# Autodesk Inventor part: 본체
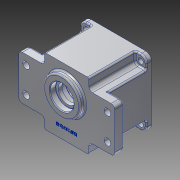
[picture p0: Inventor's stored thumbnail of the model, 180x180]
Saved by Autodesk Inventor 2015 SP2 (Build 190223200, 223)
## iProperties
Created: 2015-06
Part Number: 본체
Material: 알루미늄 6061
Document SubType Name: Modeling
Designer: AMC
Density: 2.7 g/cm^3
Appearance: 알루미늄 - 평지
Mass: 702.824 g
Surface Area: 672.969 cm^2
Volume: 260.305 cm^3
Author: AMC
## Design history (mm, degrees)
sketch "스케치1"
  geometry: L1 (45, 45)-(-45, 45); L2 (-45, 45)-(-45, -45); L3 (-45, -45)-(45, -45); L4 (45, -45)-(45, 45); 3 further points
  constraints: 8 end point, 2 midpoint, 2 parallel, 2 perpendicular, 1 horizontal, 1 horizontal alignment, 1 vertical alignment
  dimensions: "d0" = 90 distance of L1.start L1.end
extrude "돌출1" new body sketch "스케치1" distance "d1" = 70; taper "d2" = 0 deg
sketch "스케치2"
  geometry: L1 (-65, 30)-(65, 30); L2 (65, 30)-(65, -30); L3 (65, -30)-(-65, -30); L4 (-65, -30)-(-65, 30); 3 further points
  constraints: 8 end point, 2 midpoint, 2 parallel, 1 horizontal, 1 horizontal alignment, 1 perpendicular, 1 vertical alignment
  dimensions: "d3" = 130 distance of L2.end L3.end; "d4" = 60 distance of L1.end L2.end
extrude "돌출2" join sketch "스케치2" distance "d5" = 12; taper "d6" = 0 deg
sketch "스케치3"
  geometry: L1 (-45, 45)-(45, 45) reference; L2 (45, 45)-(45, -45) reference; L3 (45, 30)-(30, 30); L4 (30, 30)-(30, 45); 1 further point
  constraints: 4 end point, 2 perpendicular, 2 point on line
  dimensions: "d7" = 15 distance between parallel lines of L1 L3; "d8" = 30 distance from line of point (0, 0) L4
extrude "돌출3" cut sketch "스케치3" distance "d9" = 63; taper "d10" = 0 deg
sketch "스케치4"
  geometry: C1 r 25 at (0, 11); 1 further point
  constraints: 1 centre point, 1 vertical alignment
  dimensions: "d14" = 50 diameter of C1; "d15" = 11 distance of point (0, 0) C1.centre
extrude "돌출4" join sketch "스케치4" distance "d16" = 7; taper "d17" = 0 deg
fillet "모깎기1" dims "d18" = 5
fillet "모깎기2" dims "d19" = 8
sketch "스케치5"
  geometry: 3 further points
  constraints: 1 vertical alignment
  dimensions: "d20" = 35 distance of point (55, -17.5) point (55, 17.5); "d21" = 55 horizontal distance of point (0, 0) point (55, 17.5); "d22" = 17.5 vertical distance of point (55, 17.5) point (0, 0)
hole "구멍1" sketch "스케치5" at (55, 17.5), (55, -17.5) diameter "d23" = 9; stored, may be unused: countersink angle "d27" = 90 deg, drill point angle "d29" = 118 deg; dims "d24" = 6, "d25" = 4, "d26" = 2, "d28" = 8
sketch "스케치6"
  geometry: 1 further point
hole "구멍2" sketch "스케치6" at (0, 0) diameter "d30" = 78; stored, may be unused: countersink angle "d34" = 90 deg, drill point angle "d36" = 0 deg; dims "d31" = 6, "d32" = 80, "d33" = 9, "d35" = 61
sketch "스케치7"
  geometry: C1 r 25 at (0, -11) reference; C2 r 20.5 at (0, -11); 1 further point
  constraints: 1 centre point, 1 coincident
  dimensions: "d37" = 41 diameter of C2
extrude "돌출5" join sketch "스케치7" distance "d38" = 7; taper "d39" = 0 deg
hole "구멍3" diameter "d42" = 25; stored, may be unused: countersink angle "d46" = 90 deg, drill point angle "d48" = 118 deg; dims "d40" = 10, "d41" = 10, "d43" = 6, "d44" = 32, "d45" = 8, "d47" = 61
hole "구멍4" diameter "d51" = 35; stored, may be unused: countersink angle "d55" = 90 deg, drill point angle "d57" = 0 deg; dims "d49" = 10, "d50" = 10, "d52" = 6, "d53" = 32, "d54" = 8, "d56" = 10
sketch "스케치8"
  geometry: C1 r 14 at (0, 20); 1 further point
  constraints: 1 centre point, 1 vertical alignment
  dimensions: "d58" = 20 distance of point (0, 0) C1.centre; "d59" = 28 diameter of C1
extrude "돌출6" join sketch "스케치8" distance "d60" = 7; taper "d61" = 0 deg
hole "구멍5" diameter "d64" = 19; stored, may be unused: countersink angle "d68" = 90 deg, drill point angle "d70" = 0 deg; dims "d62" = 10, "d63" = 10, "d65" = 6, "d66" = 22, "d67" = 7, "d69" = 8
fillet "모깎기3" dims "d71" = 0.3
chamfer "모따기1" distance "d72" = 1; stored, may be unused: second distance "d73" = 2, angle "d74" = 45 deg
sketch "스케치9"
  geometry: L1 (0, 0)-(24.749, -24.749); L2 (0, 0)-(35, 0); L3 (22.066, -27.716)-(24.749, -30.141); L4 (27.716, -22.066)-(30.141, -24.749); A1 r 4 centre (24.749, -24.749) between (27.716, -22.066) and (22.066, -27.716); A2 r 39 centre (0, 0) between (24.749, -30.141) and (30.141, -24.749) reference; A3 r 39 centre (0, 0) between (24.749, -30.141) and (30.141, -24.749) reference
  constraints: 8 end point, 6 point on circle, 2 tangent, 1 centre point, 1 coincident, 1 equal length, 1 horizontal, 1 horizontal alignment, 1 vertical alignment
  dimensions: "d75" = 35 distance of L1.start L1.end; "d76" = 45 deg angle of L1 L2; "d77" = 8 diameter of A1
extrude "돌출7" join sketch "스케치9" distance "d78" = 52; taper "d79" = 0 deg
fillet "모깎기4" dims "d89" = 3.5
fillet "모깎기5" dims "d93" = 3
fillet "모깎기6" dims "d94" = 2
hole "구멍7" diameter "d97" = 7; stored, may be unused: countersink angle "d101" = 90 deg, drill point angle "d103" = 0 deg; dims "d95" = 10, "d96" = 10, "d98" = 12, "d99" = 22, "d100" = 7, "d102" = 15
fillet "모깎기7" dims "d110" = 2
fillet "모깎기8" dims "d111" = 2
fillet "모깎기9" dims "d112" = 2
fillet "모깎기10" dims "d113" = 2
fillet "모깎기11" dims "d114" = 2
sketch "스케치10"
  geometry: L1 (28, -45)-(-28, -45) reference; 2 further points
  constraints: 1 vertical alignment, 1 other
  dimensions: "d115" = 15 distance from line of L1 point (0, -30)
feature "엠보싱1" sketch "스케치10" dims "d116" = 0.5, "d117" = 0
fillet "모깎기12" dims "d118" = 2
hole "구멍8" diameter "d121" = 3.459; stored, may be unused: countersink angle "d125" = 90 deg, drill point angle "d127" = 118 deg; dims "d122" = 12, "d123" = 22, "d124" = 7, "d126" = 15, "d128" = 10, "d129" = 10
node "솔리드1"
pattern_linear "직사각형 패턴1" dims "d13" = 75
mirror "대칭1"
mirror "대칭2"
pattern_circular "원형 패턴1" dims angle "d91" = 360 deg
pattern_linear "직사각형 패턴2" dims "d106" = 74, "d109" = 74
pattern_circular "원형 패턴2" dims angle "d131" = 360 deg
